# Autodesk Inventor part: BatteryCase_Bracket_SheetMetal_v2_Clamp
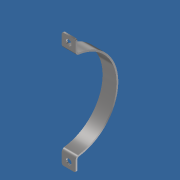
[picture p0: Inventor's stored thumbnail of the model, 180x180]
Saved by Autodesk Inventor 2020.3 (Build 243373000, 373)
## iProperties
Created: 2020-09
Part Number: BatteryCase_Bracket_SheetMetal_v2_Clamp
Material: Stainless Steel
Document SubType Name: Sheet Metal
Designer: biggshj
Manufacturer: Standard
Standards Organization: Custom
Density: 8 g/cm^3
Sheet Metal Rule: Default_mm
Appearance: Semi-Polished
Mass: 266.958 g
Surface Area: 244.003 cm^2
Volume: 33.3698 cm^3
Author: biggshj
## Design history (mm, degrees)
node "Contour Flange1"
  sketch "Sketch2"
    geometry: L1 (0, 0)-(-5, 0); L2 (0, 77.84)-(0, 102.84); L3 (0, -77.84)-(0, -102.84); L4 (0, -143.975)-(0, 143.975) reference; A1 r 78 centre (-5, 0) between (0, -77.84) and (0, 77.84)
    constraints: 6 end point, 2 collinear, 2 point on circle, 2 vertical, 1 centre point, 1 coincident, 1 horizontal
    dimensions: "d0" = 5 distance of L1.start L1.end; "d1" = 78 radius of A1; "d2" = 25 distance of L2.start L2.end; "d3" = 25 distance of L3.start L3.end
sketch "Sketch3"
  geometry: L1 (0, 102.84)-(0, 10.84); L2 (0, 10.84)-(12.5, 10.84); C1 r 5 at (12.5, 10.84)
  constraints: 4 end point, 1 centre point, 1 coincident, 1 perpendicular, 1 vertical
  dimensions: "d15" = 92 distance of L1.start L1.end; "d16" = 12.5 distance of L1.end L2.end; "d18" = 10 diameter of C1
extrude "Extrusion1" cut sketch "Sketch3" distance "d20" = 10; taper "d21" = 0 deg
mirror "Mirror1"
feature "Corner Round1" dims "d22" = 3
body "Solid1"
face "Plate1" dims "d4" = 3 (= Thickness), "d5" = 3 (= BendReliefWidth), "d6" = 1.5 (= BendReliefDepth), "d7" = 6 (= MinimumRemnant), "d8" = 3 (= TransitionRadius), "d9" = 25, "d10" = 3 (= BendRadius), "d11" = 3, "d12" = 12 (= CornerReliefSize), "d13" = 3 (= GapSize), "d14" = 3 (= JacobiRadiusSize), "SeamGap" = 0.01
bend "Bend1" dims "d4" = 3 (= Thickness), "d5" = 3 (= BendReliefWidth), "d6" = 1.5 (= BendReliefDepth), "d7" = 6 (= MinimumRemnant), "d8" = 3 (= TransitionRadius), "d10" = 3 (= BendRadius), "d11" = 3, "SeamGap" = 0.01
feature "Corner1" dims "d11" = 3, "d12" = 12 (= CornerReliefSize), "d13" = 3 (= GapSize), "d14" = 3 (= JacobiRadiusSize)
other parameters: "Thickness" = 3 (derived), "BendRadius" = 3 (= Thickness), "BendReliefWidth" = 3 (= Thickness), "BendReliefDepth" = 1.5 (= 0.5 x Thickness), "CornerReliefSize" = 12 (= 4 x Thickness), "MinimumRemnant" = 6 (= 2 x Thickness), "TransitionRadius" = 3 (= BendRadius), "JacobiRadiusSize" = 3 (= BendRadius), "GapSize" = 3 (= Thickness)
